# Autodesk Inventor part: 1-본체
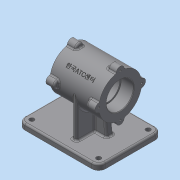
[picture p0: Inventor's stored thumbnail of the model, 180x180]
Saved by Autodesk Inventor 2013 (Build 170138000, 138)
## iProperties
Created: 2015-12
Part Number: 1-본체
Material: 일반
Document SubType Name: Modeling
Designer: ST1
Density: 1 g/cm^3
Author: ST1
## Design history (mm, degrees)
sketch "스케치1"
  geometry: L1 (0, 0)-(85, 0); L2 (0, 23.5)-(22, 23.5); L3 (22, 23.5)-(22, 21); L4 (22, 21)-(63, 21); L5 (63, 21)-(63, 23.5); L6 (63, 23.5)-(85, 23.5); L7 (0, 23.5)-(0, 37); L8 (0, 37)-(85, 37); L9 (85, 37)-(85, 23.5)
  constraints: 18 end point, 6 perpendicular, 2 parallel, 2 vertical alignment, 1 horizontal, 1 horizontal alignment
  dimensions: "d0" = 85 distance of L1.start L1.end; "d1" = 47 diameter of L2 L1; "d2" = 22 distance of L2.start L2.end; "d3" = 42 diameter of L4 L1; "d4" = 41 distance of L3.end L4.end; "d5" = 74 diameter of L8 L1
revolve "회전1" sketch "스케치1" stored, may be unused: angle "d6" = 90 deg
sketch "스케치2"
  geometry: C1 r 23.5 at (0, 0) reference; C2 r 7 at (0, 37); C3 r 7 at (37, 0); C4 r 7 at (-37, 0); C5 r 7 at (0, -37); A1 r 37 centre (0, 0) between (0, 37) and (37, 0) reference
  constraints: 4 centre point, 4 point on circle, 3 equal radius, 2 horizontal alignment, 2 vertical alignment
  dimensions: "d7" = 14 diameter of C2
extrude "돌출1" join sketch "스케치2" distance "d9" = 15; taper "d10" = 0 deg
node "작업 평면1"
sketch "스케치3"
  geometry: A1 r 7 centre (0, 0) between (-0.662, -6.969) and (-0.662, 6.969) reference; A2 r 7 centre (-37, 37) between (-30.031, 36.338) and (-43.969, 36.338) reference; A3 r 7 centre (-74, 0) between (-73.338, 6.969) and (-73.338, -6.969) reference; A4 r 7 centre (-37, -37) between (-43.969, -36.338) and (-30.031, -36.338) reference; 4 further points
  constraints: 4 coincident
hole "구멍1" sketch "스케치3" at (-37, 37), (0, 0), (-74, 0), (-37, -37) diameter "d11" = 3.242; stored, may be unused: countersink angle "d15" = 90 deg, drill point angle "d17" = 118 deg; dims "d12" = 9, "d13" = 4, "d14" = 2, "d16" = 11
fillet "모깎기1" dims "d18" = 0.3
chamfer "모따기1" distance "d19" = 1; stored, may be unused: second distance "d20" = 2, angle "d21" = 45 deg
fillet "모깎기2" dims "d22" = 3
sketch "스케치4"
  geometry: L1 (-37, 0)-(-79.773, 42.773); L2 (-37, 0)-(-99.297, 0); C1 r 1.621 at (-37, -37) reference; C2 r 1.621 at (0, 0) reference; C3 r 1.621 at (-37, 37) reference; C4 r 1.621 at (-74, 0) reference; C5 r 24.5 at (-37, 0) reference; A1 r 3 centre (-75.77, -9.842) between (-72.862, -9.104) and (-75.239, -6.889) reference; A2 r 7 centre (-74, 0) between (-75.239, 6.889) and (-75.239, -6.889) reference; A3 r 3 centre (-75.77, 9.842) between (-75.239, 6.889) and (-72.862, 9.104) reference; A4 r 37 centre (-37, 0) between (-46.104, 35.862) and (-72.862, 9.104) reference; A5 r 3 centre (-46.842, 38.77) between (-46.104, 35.862) and (-43.889, 38.239) reference; A6 r 7 centre (-37, 37) between (-30.111, 38.239) and (-43.889, 38.239) reference; A7 r 3 centre (-27.158, 38.77) between (-30.111, 38.239) and (-27.896, 35.862) reference; A8 r 37 centre (-37, 0) between (-1.138, 9.104) and (-27.896, 35.862) reference; A9 r 3 centre (1.77, 9.842) between (-1.138, 9.104) and (1.239, 6.889) reference; A10 r 7 centre (0, 0) between (1.239, -6.889) and (1.239, 6.889) reference; A11 r 3 centre (1.77, -9.842) between (1.239, -6.889) and (-1.138, -9.104) reference; A12 r 37 centre (-37, 0) between (-27.896, -35.862) and (-1.138, -9.104) reference; A13 r 3 centre (-27.158, -38.77) between (-27.896, -35.862) and (-30.111, -38.239) reference; A14 r 7 centre (-37, -37) between (-43.889, -38.239) and (-30.111, -38.239) reference; A15 r 3 centre (-46.842, -38.77) between (-43.889, -38.239) and (-46.104, -35.862) reference; A16 r 37 centre (-37, 0) between (-72.862, -9.104) and (-46.104, -35.862) reference; 1 further point
  constraints: 4 end point, 1 horizontal
  dimensions: "d23" = 45 deg angle of L2 L1
  node "투영된 루프1"
node "작업 평면2"
sketch "스케치5"
  geometry: L1 (-42.5, 18.921)-(-42.5, -18.921) reference; 2 further points
  constraints: 1 horizontal alignment, 1 other
  dimensions: "d24" = 42.5 distance from line of point (0, 0) L1
feature "엠보싱1" sketch "스케치5" dims "d0" = 85, "d1" = 47, "d2" = 22, "d3" = 42, "d4" = 41, "d5" = 74, "d25" = 0.5, "d26" = 0
node "작업 평면3"
sketch "스케치6"
  geometry: L1 (-17.5, 55)-(122.5, 55); L2 (122.5, 55)-(122.5, -55); L3 (122.5, -55)-(-17.5, -55); L4 (-17.5, -55)-(-17.5, 55); L5 (18, 37)-(67, 37) reference; L6 (0, 9.104)-(0, 35.862) reference; 3 further points
  constraints: 8 end point, 2 midpoint, 2 parallel, 1 horizontal, 1 horizontal alignment, 1 perpendicular
  dimensions: "d28" = 110 distance of L1.end L2.end; "d30" = 140 distance of L1.start L1.end; "d46" = 80 distance from line of L2 point (42.5, 37)
extrude "돌출2" join sketch "스케치6" distance "d31" = 10; taper "d32" = 0 deg
fillet "모깎기3" dims "d33" = 12
sketch "스케치7"
  geometry: C1 r 4 at (-5.5, 43); C2 r 4 at (110.5, 43); C3 r 4 at (110.5, -43); C4 r 4 at (-5.5, -43); A1 r 12 centre (110.5, -43) between (110.5, -55) and (122.5, -43) reference; A2 r 12 centre (110.5, 43) between (122.5, 43) and (110.5, 55) reference; A3 r 12 centre (-5.5, 43) between (-5.5, 55) and (-17.5, 43) reference; A4 r 12 centre (-5.5, -43) between (-17.5, -43) and (-5.5, -55) reference; 1 further point
  constraints: 4 centre point, 4 coincident, 3 equal radius
  dimensions: "d34" = 8 diameter of C1
extrude "돌출3" cut sketch "스케치7" distance "d36" = 10; taper "d37" = 0 deg
sketch "스케치8"
  geometry: L1 (122.5, -43)-(122.5, 43) reference; L2 (-5.5, -55)-(110.5, -55) reference; L3 (56.5, -37)-(48.5, -37); L4 (48.5, -37)-(48.5, 37); L5 (48.5, 37)-(56.5, 37); L6 (56.5, 37)-(56.5, -37); 5 further points
  constraints: 8 end point, 4 midpoint, 2 parallel, 1 horizontal, 1 horizontal alignment, 1 perpendicular, 1 vertical alignment
  dimensions: "d38" = 8 distance of L3.start L3.end; "d41" = 74 distance of L3.end L4.end
extrude "돌출4" join sketch "스케치8" stored distance "d42" = 10; taper "d43" = 0 deg
sketch "스케치9"
  geometry: L1 (0, 74)-(70, 74) reference; L2 (0, 0)-(0, 74) reference; L3 (0, 0)-(70, 0) reference; A1 r 37 centre (70, 37) between (70, 74) and (70, 0) reference
sketch "스케치10"
  geometry: L1 (0, 0)-(-70, 0) reference; L2 (0, 74)-(0, 0) reference; L3 (0, 74)-(-70, 74) reference; A1 r 37 centre (-70, 37) between (-70, 0) and (-70, 74) reference
extrude "돌출6" cut sketch "스케치10" distance "d49" = 10; taper "d50" = 0 deg
extrude "돌출9" join sketch "스케치9" distance "d64" = 8; taper "d65" = 0 deg
sketch "스케치14"
  geometry: L1 (70, 74)-(0, 74) reference; L2 (0, 0)-(0, 74) reference; L3 (0, 0)-(70, 0) reference; A1 r 37 centre (70, 37) between (70, 74) and (70, 0) reference
extrude "돌출10" join sketch "스케치14" distance "d66" = 2; taper "d67" = 0 deg
sketch "스케치15"
  geometry: L1 (0, 0)-(-70, 0) reference; L2 (0, 74)-(0, 0) reference; L3 (-70, 74)-(0, 74) reference; A1 r 37 centre (-70, 37) between (-70, 0) and (-70, 74) reference
extrude "돌출11" cut sketch "스케치15" distance "d68" = 2; taper "d69" = 0 deg
sketch "스케치16"
  geometry: L1 (46.5, -37)-(38.5, -37) reference; L2 (67.5, -6)-(17.5, -6); L3 (17.5, -6)-(17.5, 6); L4 (17.5, 6)-(67.5, 6); L5 (67.5, 6)-(67.5, -6); 4 further points
  constraints: 8 end point, 3 midpoint, 2 parallel, 1 horizontal, 1 horizontal alignment, 1 perpendicular, 1 vertical alignment
  dimensions: "d70" = 50 distance of L2.start L2.end; "d72" = 12 distance of L2.end L3.end
extrude "돌출12" join sketch "스케치16" stored distance "d73" = 2; taper "d74" = 0 deg
sketch "스케치17"
  geometry: L1 (21, -33.49)-(0, -33.49) reference; L2 (0, 0)-(0, -33.49) reference; L3 (29, -33.49)-(50, -33.49) reference; L4 (29, 0)-(29, -33.49) reference; L5 (50, 0)-(29, 0) reference; L6 (50, 0)-(50, -33.49) reference; L7 (50, 0)-(45.888, -33.49); L8 (0, 0)-(4.112, -33.49); L9 (-23, 0)-(93, 0) reference; 1 further point
  constraints: 4 end point, 2 point on line
  dimensions: "d75" = 97 deg angle of L5 L7; "d76" = 97 deg angle of L9 L8
extrude "돌출13" cut sketch "스케치17" stored distance "d77" = 2; taper "d78" = 0 deg
fillet "모깎기4" dims "d79" = 3
fillet "모깎기5" dims "d80" = 3
node "솔리드1"
mirror "대칭1"
mirror "대칭2"
node "투영된 루프6"
